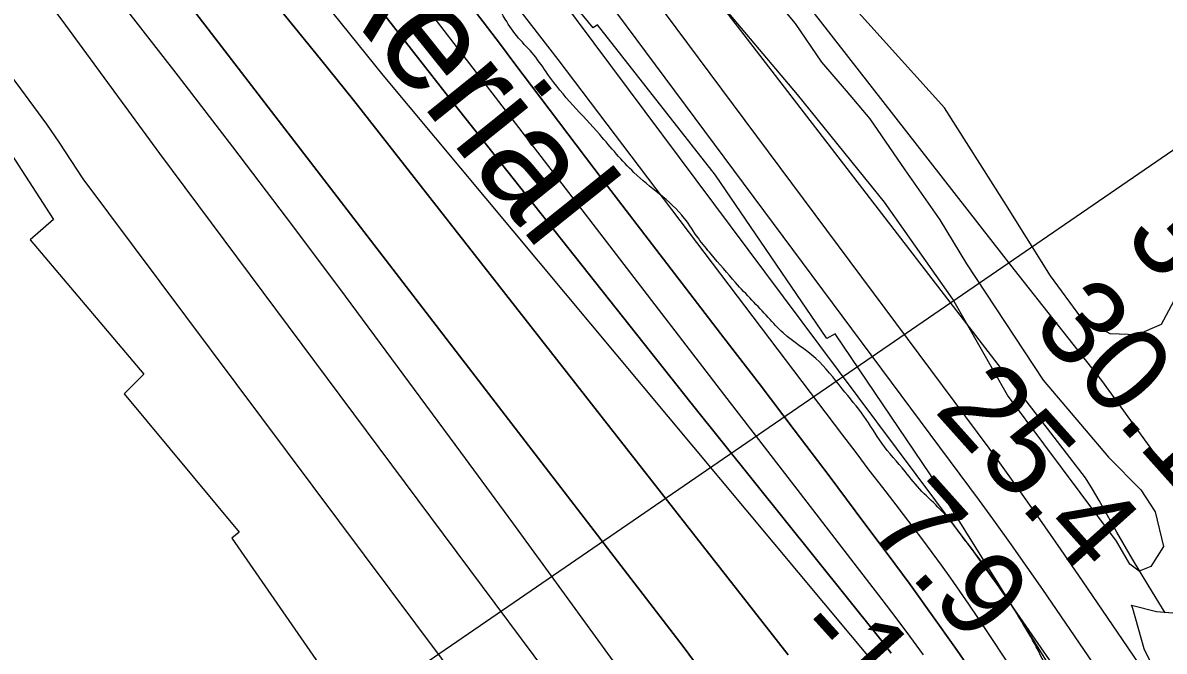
# Model space of a CAD drawing. Extents: x 3329332 to 3367211, y 631066 to 656469.
# Drawn here: x 3350592 to 3351483, y 641205 to 641695 of the extents above; entities that cross this region are included whole.
import ezdxf

# ---------------------------------------------------------------- set-up
doc = ezdxf.new("R2010")
doc.units = 0
for name, color, linetype in [('V-RIVR-EDGE', 7, 'Continuous'), ('V-RIVR-IDEN', 7, 'Continuous'), ('V-RIVR-RANG', 7, 'Continuous'), ('V-ROAD-CNTR', 7, 'Continuous'), ('V-RRAP-RVMT', 7, 'Continuous'), ('V-SITE-VEGE', 7, 'Continuous'), ('V-TOPO-DPTH', 7, 'Continuous'), ('V-TOPO-MAJR', 7, 'Continuous'), ('V-TOPO-MINR', 7, 'Continuous'), ('V-TOPO-WATR', 7, 'Continuous'), ('V-WETL-SWMP', 7, 'Continuous')]:
    doc.layers.add(name, color=color, linetype=linetype)

msp = doc.modelspace()

# ---------------------------------------------------------------- linework, layer by layer
at = {"layer": 'V-RIVR-EDGE'}
msp.add_spline([(3351880.42, 640440.17), (3351876.56, 640444.83), (3351875.03, 640453.75), (3351871.17, 640463.46), (3351865.76, 640470.06), (3351847.23, 640503.46), (3351818.65, 640553.56), (3351810.16, 640569.09), (3351795.85, 640585.8), (3351792.76, 640587.75), (3351786.18, 640593.97), (3351758.32, 640620.8), (3351741.3, 640637.51), (3351732.8, 640648.78), (3351730.49, 640655.38), (3351728.17, 640658.88), (3351720.05, 640667.43), (3351711.55, 640681.02), (3351709.62, 640686.46), (3351709.64, 640692.27), (3351709.27, 640701.97), (3351709.29, 640708.17), (3351711.63, 640715.54), (3351715.92, 640722.89), (3351717.5, 640736.07), (3351718.73, 640762.05), (3351717.22, 640778.35), (3351714.53, 640790.37), (3351713.37, 640790.76), (3351699.41, 640791.96), (3351689.73, 640796.25), (3351681.22, 640805.97), (3351671.17, 640818.02), (3351661.91, 640838.2), (3351651.08, 640851.42), (3351642.96, 640859.58), (3351631.34, 640865.04), (3351621.66, 640871.65), (3351610.83, 640881.38), (3351596.9, 640895.37), (3351584.51, 640905.1), (3351577.55, 640911.71), (3351552.78, 640932.32), (3351530.73, 640953.71), (3351519.12, 640964.21), (3351513.32, 640971.98), (3351507.16, 640987.12), (3351502.9, 640991), (3351492.83, 640996.85), (3351483.55, 641008.11), (3351471.59, 641031.02), (3351466.18, 641038.02), (3351459.21, 641043.85), (3351454.56, 641046.97), (3351449.54, 641056.29), (3351444.54, 641069.48), (3351431.43, 641103.26), (3351426.44, 641123.05), (3351423.74, 641129.26), (3351417.17, 641135.48), (3351410.99, 641147.13), (3351408.29, 641152.56), (3351407.13, 641154.12), (3351401.31, 641154.13), (3351396.67, 641158.8), (3351396.29, 641162.29), (3351398.23, 641164.61), (3351403.29, 641168.48), (3351403.3, 641173.52), (3351399.46, 641188.65), (3351394.81, 641192.15), (3351390.17, 641195.65), (3351385.92, 641202.65), (3351374.34, 641223.62), (3351352.32, 641258.18), (3351324.49, 641295.48), (3351308.25, 641315.3), (3351293.94, 641329.3), (3351280.79, 641344.84), (3351262.62, 641366.99), (3351248.71, 641387.97), (3351231.7, 641409.34), (3351211.2, 641433.04), (3351185.66, 641452.89), (3351174.05, 641464.94), (3351148.52, 641492.15), (3351129.58, 641514.3), (3351119.52, 641526.73), (3351108.7, 641542.27), (3351088.97, 641561.32), (3351069.24, 641578.05), (3351042.55, 641607.59), (3351001.95, 641654.61), (3350991.13, 641669.76), (3350979.14, 641682.98), (3350968.7, 641697.74), (3350957.9, 641718.32), (3350945.94, 641745.11), (3350930.11, 641774.23), (3350917.74, 641788.22), (3350908.85, 641801.43), (3350900.74, 641814.64), (3350886.81, 641828.24), (3350867.48, 641850.4), (3350846.19, 641865.96), (3350833.81, 641880.34), (3350825.7, 641891.22), (3350823.78, 641901.31), (3350821.87, 641913.33), (3350814.53, 641925.76), (3350807.19, 641935.09), (3350774.28, 641956.11), (3350737.11, 641982.18), (3350728.22, 641990.74), (3350716.62, 642008.22), (3350699.61, 642028.04), (3350681.44, 642049.41), (3350672.55, 642061.45), (3350665.99, 642076.98), (3350661.76, 642090.95), (3350651.31, 642098.74), (3350621.11, 642117.43), (3350608.73, 642131.03), (3350602.16, 642140.35), (3350596.36, 642145.02), (3350579.69, 642150.49), (3350575.44, 642153.6), (3350553.39, 642176.15), (3350549.13, 642181.2), (3350546.44, 642189.35), (3350542.19, 642195.18), (3350532.13, 642204.9), (3350519.75, 642218.89), (3350511.24, 642226.28), (3350489.16, 642235.64), (3350466.31, 642247.72), (3350456.25, 642257.05), (3350446.2, 642269.49), (3350443.51, 642279.19), (3350448.18, 642287.71), (3350448.6, 642298.96), (3350443.19, 642308.28), (3350431.97, 642318.77), (3350419.19, 642325.4), (3350405.63, 642329.7), (3350394, 642331.67), (3350385.08, 642332.08), (3350382.37, 642334.8), (3350380.44, 642339.46), (3350380.07, 642346.82), (3350385.13, 642354.57), (3350386.7, 642361.93), (3350384.01, 642369.31), (3350373.59, 642391.44), (3350360.43, 642400.39), (3350342.6, 642404.7), (3350325.92, 642404.74), (3350320.1, 642403.2), (3350313.9, 642402.44), (3350303.83, 642408.67), (3350298.79, 642411.79), (3350296.48, 642416.84), (3350298.44, 642426.14), (3350307.02, 642442.79), (3350316.75, 642460.61), (3350320.25, 642463.7), (3350322.2, 642467.19), (3350321.45, 642477.27), (3350312.94, 642488.15), (3350302.1, 642494.38), (3350278.07, 642501.03), (3350262.19, 642505.73), (3350248.64, 642515.46), (3350230.85, 642536.44), (3350216.17, 642559.36)], degree=3, dxfattribs=at)
at = {"layer": 'V-RIVR-RANG'}
msp.add_line((3351900.19, 641876.79), (3350691.24, 641047.57), dxfattribs=at)
at = {"layer": 'V-ROAD-CNTR'}
msp.add_lwpolyline([(3351492.65, 641335.56), (3351434.25, 641415.79), (3351366.18, 641502.05), (3351179.75, 641741.33), (3351119.1, 641821.57), (3351093.17, 641849.35), (3351045, 641898.18), (3350968.73, 641985.99), (3350894.62, 642060.35), (3350855.32, 642097.18), (3350807.11, 642140.78), (3350775.27, 642177.55), (3350722.86, 642262.97), (3350691.83, 642307.94), (3350641.54, 642374.69), (3350530.63, 642526.9), (3350449.36, 642647.58)], dxfattribs=at)
at = {"layer": 'V-RRAP-RVMT'}
for p, q in [((3351037.43, 641691), (3350959.88, 641784.68)), ((3351040.82, 641693.36), (3351037.43, 641691)), ((3351132.82, 641576.09), (3351040.82, 641693.36)), ((3350535.17, 641666.15), (3350616.29, 641541.4)), ((3351219.74, 641448.58), (3351132.82, 641576.09)), ((3350616.29, 641541.4), (3350597.92, 641525.43)), ((3350597.92, 641525.43), (3350686.63, 641420.7)), ((3351226.26, 641452.1), (3351219.74, 641448.58)), ((3351300.65, 641342.18), (3351226.26, 641452.1)), ((3350686.63, 641420.7), (3350671.36, 641405.51)), ((3350671.36, 641405.51), (3350761.22, 641297.43)), ((3351395.99, 641189.71), (3351300.65, 641342.18)), ((3350761.22, 641297.43), (3350755.27, 641292.72)), ((3350755.27, 641292.72), (3350838.38, 641173.25))]:
    msp.add_line(p, q, dxfattribs=at)
at = {"layer": 'V-SITE-VEGE'}
for points in [[(3351168.28, 641726.45), (3351194.92, 641694.19), (3351215.6, 641664.21), (3351234.85, 641641.7), (3351253.36, 641619.94), (3351280.69, 641580.22), (3351308.04, 641541.24), (3351328.69, 641506.78), (3351388.52, 641416.11), (3351439.59, 641356.09), (3351464.79, 641330.55), (3351475.86, 641313.32), (3351482.39, 641286.42), (3351472.59, 641270.82), (3351463.61, 641267.15), (3351456.19, 641272.42), (3351445.86, 641290.4), (3351360.83, 641404.36), (3351318.06, 641479.25), (3351264.86, 641554.96), (3351196.78, 641638.97), (3351123.51, 641726)], [(3351490.39, 641477.35), (3351480.57, 641459.51), (3351461.86, 641451.43), (3351440.98, 641452.32), (3351417.94, 641465.16), (3351394.28, 641497.39), (3351358.11, 641555.08), (3351311.6, 641628.5), (3351239.77, 641708.06)]]:
    msp.add_lwpolyline(points, dxfattribs=at)
at = {"layer": 'V-TOPO-DPTH'}
for points in [[(3349352.91, 643048.8), (3350048.09, 642577.87), (3350074.83, 642556.17), (3350100.96, 642533.79), (3350126.19, 642510.39), (3350150.8, 642486.31), (3350622.83, 642005.88), (3350643.71, 641984.13), (3350664.24, 641962.05), (3350684.25, 641939.51), (3350703.91, 641916.64), (3350723.18, 641893.44), (3350742.27, 641870.09), (3350761.1, 641846.53), (3350779.75, 641822.83), (3350865.7, 641712.37), (3350927.37, 641633.48), (3351113.97, 641398.04), (3351260.01, 641215.87), (3351265.01, 641209.56), (3351269.96, 641203.19)], [(3349352.91, 643048.8), (3350048.09, 642577.87), (3350074.83, 642556.17), (3350100.96, 642533.79), (3350126.19, 642510.39), (3350150.8, 642486.31), (3350622.83, 642005.88), (3350643.71, 641984.13), (3350664.24, 641962.05), (3350684.25, 641939.51), (3350703.91, 641916.64), (3350723.18, 641893.44), (3350742.27, 641870.09), (3350761.1, 641846.53), (3350779.75, 641822.83), (3350865.7, 641712.37), (3350927.37, 641633.48), (3351113.97, 641398.04), (3351260.01, 641215.87), (3351265.01, 641209.56), (3351269.96, 641203.19)], [(3351189.47, 641201.7), (3350850.61, 641634.21), (3350824.56, 641666.49), (3350798.35, 641698.65), (3350771.25, 641731.66), (3350758.5, 641747.24), (3350745.78, 641762.84), (3350733.12, 641778.49), (3350720.49, 641794.16), (3350704.58, 641813.94), (3350699.92, 641819.73), (3350695.24, 641825.51), (3350690.55, 641831.28), (3350685.84, 641837.03), (3350527.64, 642030.05), (3350457.08, 642114.01), (3350385.18, 642196.79), (3350311.27, 642277.77), (3350236.02, 642357.56), (3350112.21, 642485.67), (3350097.57, 642500.19), (3350082.54, 642514.28), (3350066.94, 642527.72), (3349333.19, 643026.35)], [(3349333.19, 643026.35), (3350066.94, 642527.72), (3350082.54, 642514.28), (3350097.57, 642500.19), (3350112.21, 642485.67), (3350236.02, 642357.56), (3350311.27, 642277.77), (3350385.18, 642196.79), (3350457.08, 642114.01), (3350527.64, 642030.05), (3350685.84, 641837.03), (3350690.55, 641831.28), (3350695.24, 641825.51), (3350699.92, 641819.73), (3350704.58, 641813.94), (3350720.49, 641794.16), (3350733.12, 641778.49), (3350745.78, 641762.84), (3350758.5, 641747.24), (3350771.25, 641731.66), (3350798.35, 641698.65), (3350824.56, 641666.49), (3350850.61, 641634.21), (3351189.47, 641201.7)], [(3351398.1, 641191.14), (3351380.09, 641217.36), (3351352.47, 641257.08), (3351348.09, 641263.31), (3351343.67, 641269.51), (3351339.19, 641275.67), (3351334.67, 641281.8), (3351228.86, 641423.64), (3351171.39, 641500.67), (3350851.42, 641929.24), (3350848.91, 641932.62), (3350846.41, 641936), (3350843.65, 641939.65), (3350841.29, 641942.68), (3350838.87, 641945.65), (3350836.4, 641948.59), (3350832.92, 641952.64), (3350832.15, 641953.52), (3350830.59, 641955.26), (3350829.8, 641956.12), (3350204.43, 642622.26)], [(3351116.54, 641196.41), (3351107.5, 641208.34), (3350698.61, 641739.74), (3350678.72, 641765.4), (3350658.7, 641790.96), (3350638.5, 641816.38), (3350618.17, 641841.69), (3350598.67, 641865.81), (3350568.43, 641903.05), (3350538.1, 641940.23), (3350507.63, 641977.29), (3350477.08, 642014.28), (3350069.18, 642490.21), (3350064.23, 642494.86), (3350059.07, 642499.31), (3350053.79, 642503.61), (3350021.84, 642528.51), (3350013.94, 642534.41), (3350005.9, 642540.1), (3349997.63, 642545.46), (3349989.22, 642550.6), (3349980.71, 642555.61), (3349972.22, 642560.65)], [(3349972.22, 642560.65), (3349980.71, 642555.61), (3349989.22, 642550.6), (3349997.63, 642545.46), (3350005.9, 642540.1), (3350013.94, 642534.41), (3350021.84, 642528.51), (3350053.79, 642503.61), (3350059.07, 642499.31), (3350064.23, 642494.86), (3350069.18, 642490.21), (3350477.08, 642014.28), (3350507.63, 641977.29), (3350538.1, 641940.23), (3350568.43, 641903.05), (3350598.67, 641865.81), (3350618.17, 641841.69), (3350638.5, 641816.38), (3350658.7, 641790.96), (3350678.72, 641765.4), (3350698.61, 641739.74), (3351107.5, 641208.34), (3351116.54, 641196.41)], [(3351055.19, 641194.2), (3351014.96, 641249.5), (3350974.65, 641304.74), (3350934.21, 641359.89), (3350839.75, 641487.65), (3350798.13, 641543.08), (3350756.11, 641598.19), (3350713.81, 641653.1), (3350643.12, 641744.17), (3350635.92, 641753.36), (3350628.67, 641762.5), (3350621.33, 641771.58), (3350613.93, 641780.61), (3350486.88, 641934.27), (3350415.1, 642019.38), (3350342.22, 642103.51), (3350267.7, 642186.2), (3350192.08, 642267.91), (3350054.74, 642413.43), (3350037.06, 642431.29), (3350018.85, 642448.57), (3349999.84, 642464.97), (3349980.31, 642480.78), (3349884.72, 642554.47)], [(3351055.19, 641194.2), (3351014.96, 641249.5), (3350974.65, 641304.74), (3350934.21, 641359.89), (3350839.75, 641487.65), (3350798.13, 641543.08), (3350756.11, 641598.19), (3350713.81, 641653.1), (3350643.12, 641744.17), (3350635.92, 641753.36), (3350628.67, 641762.5), (3350621.33, 641771.58), (3350613.93, 641780.61), (3350486.88, 641934.27), (3350415.1, 642019.38), (3350342.22, 642103.51), (3350267.7, 642186.2), (3350192.08, 642267.91), (3350054.74, 642413.43), (3350037.06, 642431.29), (3350018.85, 642448.57), (3349999.84, 642464.97), (3349980.31, 642480.78), (3349884.72, 642554.47)], [(3351336.79, 641183.21), (3351319.63, 641207.85), (3351302.29, 641232.35), (3351284.66, 641256.65), (3351266.85, 641280.82), (3351248.68, 641305.17), (3351221.56, 641341.34), (3351194.32, 641377.43), (3351166.9, 641413.38), (3351139.36, 641449.23), (3351045.24, 641571.76), (3351010.32, 641617.75), (3350975.53, 641663.83), (3350965.01, 641677.81), (3350935.37, 641716.83)], [(3350935.37, 641716.83), (3350965.01, 641677.81), (3350975.53, 641663.83), (3351010.32, 641617.75), (3351045.24, 641571.76), (3351139.36, 641449.23), (3351166.9, 641413.38), (3351194.32, 641377.43), (3351221.56, 641341.34), (3351248.68, 641305.17), (3351266.85, 641280.82), (3351284.66, 641256.65), (3351302.29, 641232.35), (3351319.63, 641207.85), (3351336.79, 641183.21)]]:
    msp.add_lwpolyline(points, dxfattribs=at)
at = {"layer": 'V-TOPO-MAJR'}
for points in [[(3351483.88, 641234.69), (3351470.92, 641255.39), (3351458.39, 641276.35), (3351446.13, 641297.48), (3351432.17, 641322.15), (3351427.01, 641331.02), (3351421.73, 641339.8), (3350910.65, 642003.01), (3350904.47, 642010.38), (3350898.26, 642017.72), (3350891.98, 642025.01), (3350885.67, 642032.27), (3350879.36, 642039.53), (3350873.1, 642046.83), (3350866.9, 642054.19), (3350860.75, 642061.59), (3350853.05, 642070.95), (3350843.15, 642083.11), (3350833.34, 642095.35), (3350823.68, 642107.7), (3350814.11, 642120.12), (3350339.22, 642702.32)], [(3351031.77, 641146.95), (3350699.31, 641592.8), (3350625.85, 641693.02), (3350611.34, 641712.69), (3350596.74, 641732.3), (3350582.03, 641751.82)]]:
    msp.add_lwpolyline(points, dxfattribs=at)
at = {"layer": 'V-TOPO-MINR'}
for points in [[(3351459.7, 641148.58), (3351388.27, 641252.75), (3351376.13, 641270.28), (3351363.88, 641287.72), (3351351.47, 641305.06), (3351338.94, 641322.31), (3350871.7, 641950.51), (3350861.74, 641962.12), (3350851.7, 641973.65), (3350841.53, 641985.07), (3350831.28, 641996.42), (3350404.3, 642460.49), (3350342.05, 642526.19), (3350242.08, 642631.03), (3350229.4, 642643.89), (3350216.44, 642656.46), (3350203.07, 642668.59), (3350189.43, 642680.43), (3349449, 643139.02), (3349438.18, 643146.14), (3349427.82, 643153.94), (3349417.78, 643162.18), (3348731.92, 643884.66)], [(3351269.96, 641203.19), (3351265.01, 641209.56), (3351260.01, 641215.87), (3351113.97, 641398.04), (3350927.37, 641633.48), (3350865.7, 641712.37), (3350779.75, 641822.83), (3350761.1, 641846.53), (3350742.27, 641870.09), (3350723.18, 641893.44), (3350703.91, 641916.64), (3350684.25, 641939.51), (3350664.24, 641962.05), (3350643.71, 641984.13), (3350622.83, 642005.88), (3350150.8, 642486.31), (3350126.19, 642510.39), (3350100.96, 642533.79), (3350074.83, 642556.17), (3350048.09, 642577.87), (3349352.91, 643048.8)], [(3351189.47, 641201.7), (3350850.61, 641634.21), (3350824.56, 641666.49), (3350798.35, 641698.65), (3350771.25, 641731.66), (3350758.5, 641747.24), (3350745.78, 641762.84), (3350733.12, 641778.49), (3350720.49, 641794.16), (3350704.58, 641813.94), (3350699.92, 641819.73), (3350695.24, 641825.51), (3350690.55, 641831.28), (3350685.84, 641837.03), (3350527.64, 642030.05), (3350457.08, 642114.01), (3350385.18, 642196.79), (3350311.27, 642277.77), (3350236.02, 642357.56), (3350112.21, 642485.67), (3350097.57, 642500.19), (3350082.54, 642514.28), (3350066.94, 642527.72), (3349333.19, 643026.35)], [(3351258.18, 641193.5), (3350873.49, 641654.12), (3350834.47, 641702.25), (3350795.69, 641750.57), (3350747.64, 641810.88), (3350733, 641829.14), (3350718.29, 641847.35), (3350703.48, 641865.47), (3350688.59, 641883.54), (3350618.93, 641967.58), (3350568.47, 642027), (3350517.07, 642085.58), (3350464.29, 642142.9), (3350410.57, 642199.39), (3350131.46, 642485.94), (3350111.85, 642505.26), (3350091.74, 642524.02), (3350070.88, 642541.94), (3350049.52, 642559.31), (3349371.33, 643017.74)], [(3351629.34, 640951.72), (3351419.32, 641259.64), (3351402.75, 641283.71), (3351386.06, 641307.68), (3351369.16, 641331.52), (3351352.14, 641355.27), (3351346.46, 641363.11), (3350893.59, 641971.31), (3350873.73, 641994.53), (3350853.67, 642017.56), (3350833.46, 642040.48), (3350778.27, 642102.53), (3350730.54, 642156.54), (3350275.84, 642687.43)], [(3351398.1, 641191.14), (3351380.09, 641217.36), (3351352.47, 641257.08), (3351348.09, 641263.31), (3351343.67, 641269.51), (3351339.19, 641275.67), (3351334.67, 641281.8), (3351228.86, 641423.64), (3351171.39, 641500.67), (3350851.42, 641929.24), (3350848.91, 641932.62), (3350846.41, 641936), (3350843.65, 641939.65), (3350841.29, 641942.68), (3350838.87, 641945.65), (3350836.4, 641948.59), (3350832.92, 641952.64), (3350832.15, 641953.52), (3350830.59, 641955.26), (3350829.8, 641956.12), (3350204.43, 642622.26)], [(3351116.54, 641196.41), (3351107.5, 641208.34), (3350698.61, 641739.74), (3350678.72, 641765.4), (3350658.7, 641790.96), (3350638.5, 641816.38), (3350618.17, 641841.69), (3350598.67, 641865.81), (3350568.43, 641903.05), (3350538.1, 641940.23), (3350507.63, 641977.29), (3350477.08, 642014.28), (3350069.18, 642490.21), (3350064.23, 642494.86), (3350059.07, 642499.31), (3350053.79, 642503.61), (3350021.84, 642528.51), (3350013.94, 642534.41), (3350005.9, 642540.1), (3349997.63, 642545.46), (3349989.22, 642550.6), (3349980.71, 642555.61), (3349972.22, 642560.65)], [(3351295.16, 641201.85), (3351284.55, 641216.35), (3351273.78, 641230.74), (3351262.89, 641245.03), (3351189.63, 641340.08), (3351142.04, 641401.85), (3350999.37, 641587.24), (3350862.95, 641764.69), (3350852.66, 641778.13), (3350842.41, 641791.59), (3350832.2, 641805.1), (3350822.03, 641818.63), (3350819.33, 641822.23), (3350810.46, 641833.92), (3350801.49, 641845.52), (3350792.36, 641857.01), (3350783.13, 641868.41), (3350771.01, 641883.18), (3350767.74, 641887.12), (3350764.42, 641891.01), (3350761.06, 641894.86), (3350757.65, 641898.68), (3350149.19, 642558.38)], [(3351055.19, 641194.2), (3351014.96, 641249.5), (3350974.65, 641304.74), (3350934.21, 641359.89), (3350839.75, 641487.65), (3350798.13, 641543.08), (3350756.11, 641598.19), (3350713.81, 641653.1), (3350643.12, 641744.17), (3350635.92, 641753.36), (3350628.67, 641762.5), (3350621.33, 641771.58), (3350613.93, 641780.61), (3350486.88, 641934.27), (3350415.1, 642019.38), (3350342.22, 642103.51), (3350267.7, 642186.2), (3350192.08, 642267.91), (3350054.74, 642413.43), (3350037.06, 642431.29), (3350018.85, 642448.57), (3349999.84, 642464.97), (3349980.31, 642480.78), (3349884.72, 642554.47)], [(3351038.32, 641039.59), (3350639.3, 641573.23), (3350630.02, 641587.53), (3350620.55, 641601.69), (3350610.89, 641615.73), (3350600.94, 641629.56), (3350590.81, 641643.26), (3350566.41, 641675.55), (3350560.22, 641683.69), (3350554, 641691.8), (3350547.73, 641699.88), (3350541.43, 641707.93), (3350428.49, 641851.32), (3350364.76, 641930.25), (3350299.78, 642008.11), (3350232.94, 642084.37), (3350164.86, 642159.58), (3349996.35, 642341.22), (3349975.93, 642362.27)], [(3351618.41, 640808.92), (3351337.48, 641230.98), (3351330.56, 641241.24), (3351323.57, 641251.45), (3351316.46, 641261.58), (3351309.27, 641271.65), (3351301.98, 641281.64), (3351294.62, 641291.59), (3351287.15, 641301.46), (3351279.62, 641311.27), (3351273.8, 641318.78), (3351263.34, 641332.34), (3351252.9, 641345.92), (3351242.52, 641359.53), (3351232.17, 641373.17), (3351009.94, 641666.17), (3350958.99, 641732.22)]]:
    msp.add_lwpolyline(points, dxfattribs=at)
at = {"layer": 'V-TOPO-WATR'}
msp.add_lwpolyline([(3351336.79, 641183.21), (3351319.63, 641207.85), (3351302.29, 641232.35), (3351284.66, 641256.65), (3351266.85, 641280.82), (3351248.68, 641305.17), (3351221.56, 641341.34), (3351194.32, 641377.43), (3351166.9, 641413.38), (3351139.36, 641449.23), (3351045.24, 641571.76), (3351010.32, 641617.75), (3350975.53, 641663.83), (3350965.01, 641677.81), (3350935.37, 641716.83)], dxfattribs=at)
at = {"layer": 'V-WETL-SWMP'}
msp.add_lwpolyline([(3351480.58, 641179.63), (3351467.33, 641206.58), (3351458.59, 641237.98), (3351457.59, 641240.48), (3351476.91, 641235.71), (3351505.53, 641233.2)], dxfattribs=at)

# ---------------------------------------------------------------- texts
at = {"layer": 'V-RIVR-IDEN'}
msp.add_text('Aerial ', height=83, rotation=308.76189, dxfattribs=at).set_placement((3350818.1, 641736.98))
at = {"layer": 'V-RIVR-RANG'}
for s, rotation, p in [('30.6', 311.83833, (3351450.12, 641527.5)), ('30.1', 311.83833, (3351378.59, 641457.48)), ('25.4', 311.83833, (3351302.66, 641392.37)), ('7.9', 311.83833, (3351250.31, 641300.92)), ('-14', 312.11689, (3351190.1, 641217.79))]:
    msp.add_text(s, height=67, rotation=rotation, dxfattribs=at).set_placement(p)

doc.saveas('drawing.dxf')
